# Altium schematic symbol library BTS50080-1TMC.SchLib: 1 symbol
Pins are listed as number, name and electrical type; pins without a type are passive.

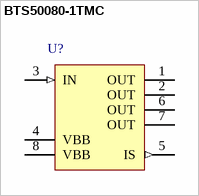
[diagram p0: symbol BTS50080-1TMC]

## BTS50080-1TMC
designator U?
Smart High-Side Power Switch PROFET, 1 Channel, 12 A Load Current, -40 to 150 degC, PG-TO220-7-4, Reel, Green; Manufacturer: Infineon; PartNumber: BTS50080-1TMC; Channels: 1; Green: TRUE; Group: Automotive Qualified; Load Current (typ): 12 A; Ptot (max): 81 W; Recommended Operating Voltage Max.: 38 V; Recommended Operating Voltage Min.: 5.5 V; RON @ 25degreesC: 8 mOhm; RON(max) @ 150degreesC: 16 mOhm; toff (max): 600 us; ton (max): 550 us
footprint INF-PG-TO220-7-4_N (DPAK, 7-Leads, Body 10x9.25mm, Pitch 1.27mm, IPC Medium Density)
footprint INF-PG-TO220-7-4_L (DPAK, 7-Leads, Body 10x9.25mm, Pitch 1.27mm, IPC High Density)
footprint INF-PG-TO220-7-4_M (DPAK, 7-Leads, Body 10x9.25mm, Pitch 1.27mm, IPC Low Density)
pins: 1 OUT (power) "Output; output to the load; pin 1, 2, 6 and 7 must be externally shorted.", 2 OUT (power) "Output; output to the load; pin 1, 2, 6 and 7 must be externally shorted.", 3 IN (in) "Input; activates the power switch if shorted to ground.", 4 VBB (power) "Supply Voltage; positive power supply voltage; tab and pin 4 are internally shorted", 5 IS (out) "Sense Output; Diagnostic feedback; provides at normal operation a sense current proportional to the load current; in case of overload, overtemperature and/or short circuit a defined current is provided (see Table 1 “Truth (See Datasheet)", 6 OUT (power) "Output; output to the load; pin 1, 2, 6 and 7 must be externally shorted.", 7 OUT (power) "Output; output to the load; pin 1, 2, 6 and 7 must be externally shorted.", 8 VBB (power) "Supply Voltage; positive power supply voltage; tab and pin 4 are internally shorted"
